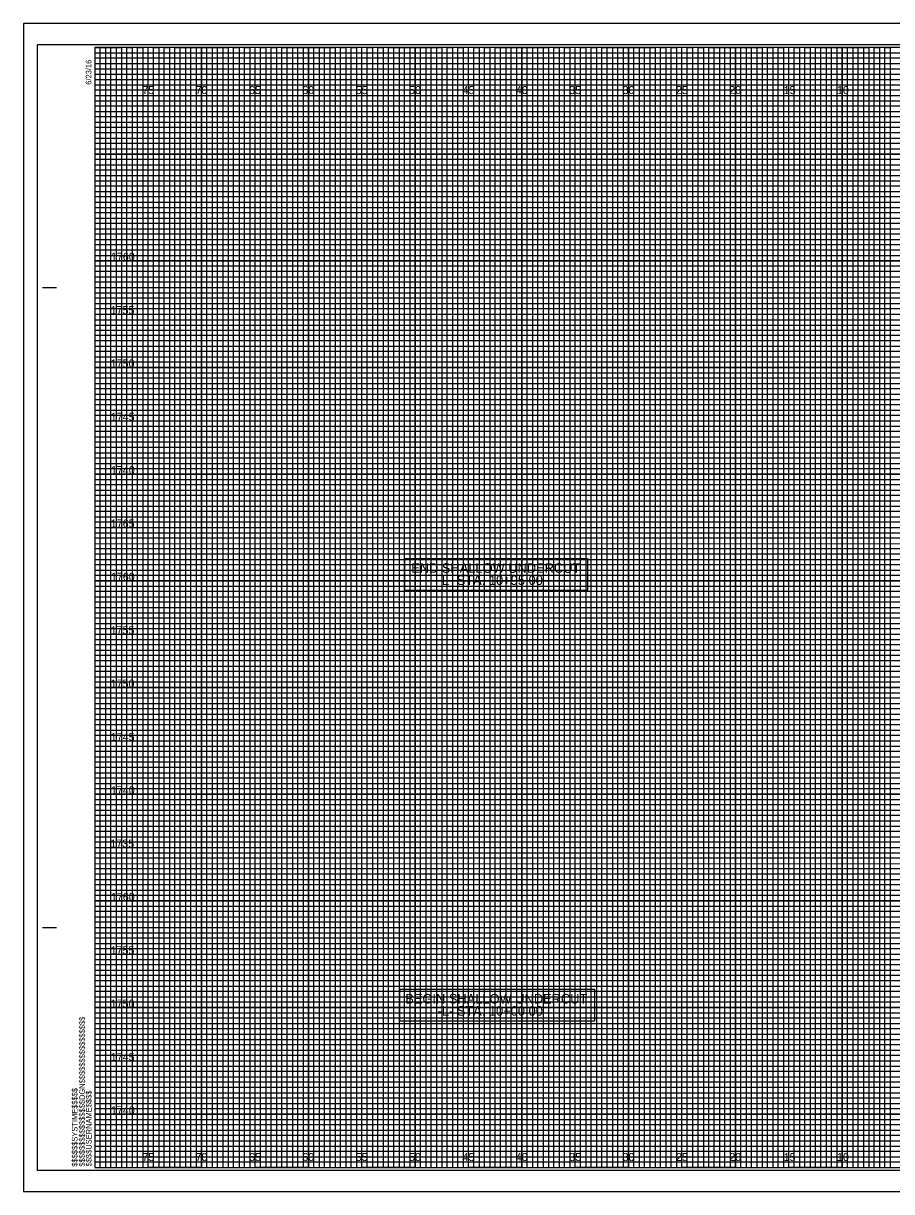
# Model space of a CAD drawing. Extents: x -7 to 162, y -2 to 107.
# Drawn here: x -6.7 to 74.6, y -2.3 to 107.3 of the extents above; entities that cross this region are included whole.
import ezdxf

# ---------------------------------------------------------------- set-up
doc = ezdxf.new("R2010")
doc.units = 0
for name, color, linetype in [('Exist XS Center Line Elevation Label', 7, 'Continuous'), ('Prop Grid Mask', 7, 'Continuous'), ('Prop XS Elevation Labels', 7, 'Continuous'), ('Prop XS Offset Labels', 7, 'Continuous'), ('Sheet Cross Section CELL', 7, 'Continuous'), ('Sheet Cross Section Grid Major CELL', 7, 'Continuous'), ('Sheet Cross Section Grid Middle CELL', 7, 'Continuous'), ('Sheet Cross Section Grid Minor 1 CELL', 7, 'Continuous'), ('Sheet Cross Section Grid Minor 2 CELL', 7, 'Continuous'), ('Sheet Cutting Line CELL', 7, 'Continuous'), ('Sheet DOT Grid CELL', 7, 'Continuous'), ('Sheet Plot Border Inside CELL', 7, 'Continuous'), ('Sheet Plot Border Outside CELL', 7, 'Continuous')]:
    doc.layers.add(name, color=color, linetype=linetype)

msp = doc.modelspace()

# ---------------------------------------------------------------- linework, layer by layer
at = {"layer": 'Prop Grid Mask'}
for points in [[(29.02, 57.09), (46.16, 57.09), (46.16, 54.1), (29.02, 54.1)], [(28.58, 16.72), (46.81, 16.72), (46.81, 13.74), (28.58, 13.74)]]:
    msp.add_lwpolyline(points, close=True, dxfattribs=at)
at = {"layer": 'Sheet Cross Section CELL'}
for p, q in [((-4.9, 82.5), (-3.65, 82.5)), ((-4.85, 82.5), (-3.6, 82.5)), ((-4.9, 22.5), (-3.65, 22.5)), ((-4.85, 22.5), (-3.6, 22.5)), ((0, 0), (0, 0)), ((0, 0), (0, 0)), ((0, 0), (0, 0)), ((0, 0), (0, 0)), ((0, 0), (0, 0)), ((0, 0), (0, 0)), ((0, 0), (0, 0))]:
    msp.add_line(p, q, dxfattribs=at)
msp.add_lwpolyline([(160, 105), (0, 105), (0, 0), (160, 0)], close=True, dxfattribs=at)
at = {"layer": 'Sheet Cross Section Grid Major CELL'}
for p, q in [((5, 105), (0, 105)), ((5, 0), (5, 105)), ((15, 105), (10, 105)), ((10, 105), (10, 0)), ((15, 0), (15, 105)), ((25, 105), (20, 105)), ((20, 105), (20, 0)), ((25, 0), (25, 105)), ((35, 105), (30, 105)), ((30, 105), (30, 0)), ((35, 0), (35, 105)), ((45, 105), (40, 105)), ((40, 105), (40, 0)), ((45, 0), (45, 105)), ((55, 105), (50, 105)), ((50, 105), (50, 0)), ((55, 0), (55, 105)), ((65, 105), (60, 105)), ((60, 105), (60, 0)), ((65, 0), (65, 105)), ((75, 105), (70, 105)), ((70, 105), (70, 0)), ((10, 0), (5, 0)), ((20, 0), (15, 0)), ((30, 0), (25, 0)), ((40, 0), (35, 0)), ((50, 0), (45, 0)), ((60, 0), (55, 0)), ((70, 0), (65, 0))]:
    msp.add_line(p, q, dxfattribs=at)
for points in [[(0, 100), (160, 100), (160, 95), (0, 95)], [(0, 90), (160, 90), (160, 85), (0, 85)], [(0, 80), (160, 80), (160, 75), (0, 75)], [(0, 70), (160, 70), (160, 65), (0, 65)], [(0, 60), (160, 60), (160, 55), (0, 55)], [(0, 50), (160, 50), (160, 45), (0, 45)], [(0, 40), (160, 40), (160, 35), (0, 35)], [(0, 30), (160, 30), (160, 25), (0, 25)], [(0, 20), (160, 20), (160, 15), (0, 15)], [(0, 10), (160, 10), (160, 5), (0, 5)]]:
    msp.add_lwpolyline(points, dxfattribs=at)
at = {"layer": 'Sheet Cross Section Grid Middle CELL'}
for points in [[(0, 105), (2.5, 105), (2.5, 0), (7.5, 0), (7.5, 105), (12.5, 105), (12.5, 0), (17.5, 0), (17.5, 105), (22.5, 105), (22.5, 0), (27.5, 0), (27.5, 105), (32.5, 105), (32.5, 0), (37.5, 0), (37.5, 105), (42.5, 105), (42.5, 0), (47.5, 0), (47.5, 105), (52.5, 105), (52.5, 0), (57.5, 0), (57.5, 105), (62.5, 105), (62.5, 0), (67.5, 0), (67.5, 105), (72.5, 105), (72.5, 0), (77.5, 0)], [(0, 102.5), (137.5, 102.5)], [(0, 92.5), (160, 92.5), (160, 97.5), (0, 97.5)], [(0, 82.5), (160, 82.5), (160, 87.5), (0, 87.5)], [(0, 72.5), (160, 72.5), (160, 77.5), (0, 77.5)], [(0, 62.5), (160, 62.5), (160, 67.5), (0, 67.5)], [(0, 52.5), (160, 52.5), (160, 57.5), (0, 57.5)], [(0, 42.5), (160, 42.5), (160, 47.5), (0, 47.5)], [(0, 32.5), (160, 32.5), (160, 37.5), (0, 37.5)], [(0, 22.5), (160, 22.5), (160, 27.5), (0, 27.5)], [(0, 12.5), (160, 12.5), (160, 17.5), (0, 17.5)], [(0, 2.5), (160, 2.5), (160, 7.5), (0, 7.5)]]:
    msp.add_lwpolyline(points, dxfattribs=at)
at = {"layer": 'Sheet Cross Section Grid Minor 1 CELL'}
for p, q in [((0, 104.5), (130, 104.5)), ((130, 103.99), (0, 103.99)), ((0, 103.99), (0, 103.5)), ((0, 103.5), (130, 103.5)), ((130, 102.95), (0, 102.95)), ((0, 102.95), (0, 102)), ((0, 102), (160, 102))]:
    msp.add_line(p, q, dxfattribs=at)
for points in [[(0, 101.5), (135, 101.5), (160, 101.5), (160, 101), (0, 101)], [(0, 100.5), (160, 100.5), (160, 99.5), (0, 99.5)], [(0, 99), (160, 99), (160, 98.5), (0, 98.49)], [(0, 98), (160, 98), (160, 97), (0, 97)], [(0, 96.5), (160, 96.5), (160, 96), (0, 96)], [(0, 95.5), (160, 95.5), (160, 94.5), (0, 94.5)], [(0, 94), (160, 94), (160, 93.5), (0, 93.5)], [(0, 93), (160, 93), (160, 92), (0, 92)], [(0, 91.5), (160, 91.5), (160, 91), (0, 91)], [(0, 90.5), (160, 90.5), (160, 89.5), (0, 89.5)], [(0, 89), (160, 89), (160, 88.5), (0, 88.5)], [(0, 88), (160, 88), (160, 86.98), (160, 86.5), (160, 86), (0, 86)], [(0, 87), (160, 87), (160, 86.5), (0, 86.5)], [(0, 85.5), (160, 85.5), (160, 84.5), (0, 84.52)], [(0, 84.52), (160, 84.5), (160, 84), (0, 84)], [(0, 83.5), (160, 83.5), (160, 83), (0, 83)], [(0, 82), (160, 82), (160, 81.5), (0, 81.5)], [(0, 81), (160, 81), (160, 80.5), (0, 80.5)], [(-0.04, 79.45), (160, 79.45), (160, 78.94), (-0.04, 78.94)], [(0, 78.5), (160, 78.5), (160, 78), (0, 78)], [(0, 77), (160, 77), (160, 76.5), (0, 76.5)], [(0, 76), (160, 76), (160, 75.5), (0, 75.5)], [(0, 74.5), (160, 74.5), (160, 74), (0, 74)], [(0, 73.5), (160, 73.5), (160, 73), (0, 73)], [(0, 72), (160, 72), (160, 71.5), (0, 71.5)], [(0, 71), (160, 71), (160, 70.5), (0, 70.5)], [(0, 69.5), (160, 69.5), (160, 68.99), (0, 69)], [(0, 68.5), (160, 68.5), (160, 68), (0, 68)], [(0, 67), (160, 67), (160, 66.5), (0, 66.5)], [(0, 66), (160, 66), (160, 65.5), (0, 65.5)], [(0, 64.5), (160, 64.5), (160, 64), (0, 64)], [(0, 63.5), (160, 63.5), (160, 63), (0, 63)], [(0, 62), (160, 62), (160, 61.5), (0, 61.5)], [(0, 61), (160, 61), (160, 60.5), (0, 60.5)], [(0, 59.5), (160, 59.5), (160, 59), (0, 59)], [(0, 58.5), (160.03, 58.45), (160, 58), (0, 58)], [(0, 57), (160, 57), (160, 56.5), (0, 56.5)], [(0, 56), (160, 56), (160, 55.5), (0, 55.5)], [(0, 54.5), (160, 54.5), (160, 54), (0, 54)], [(0, 53.5), (160, 53.5), (160, 53), (0, 53)], [(0, 52), (160, 52), (160, 51.5), (0, 51.5)], [(0, 51), (160, 51), (160, 50.5), (0, 50.5)], [(0, 49.5), (160, 49.5), (160, 49), (0, 49)], [(0, 48.5), (160, 48.5), (160, 48), (0, 48)], [(0, 47), (160, 47), (160, 46.5), (0, 46.5)], [(0, 46), (160, 46), (160, 45.5), (0, 45.5)], [(0, 44.5), (160, 44.5), (160, 44), (0, 44)], [(0, 43.5), (160, 43.5), (160, 43), (0, 43)], [(0, 42), (160, 42), (160, 41.5), (0, 41.5)], [(0, 41), (160, 41), (160, 40.5), (0, 40.5)], [(0, 39.5), (160, 39.5), (160, 38.99), (0, 39)], [(0, 38.5), (160, 38.5), (160, 38), (0, 38)], [(0, 37), (160, 37), (160, 36.5), (0, 36.5)], [(0, 36), (160, 36), (160, 35.5), (0, 35.5)], [(0, 34.5), (160, 34.5), (160, 34), (0, 34)], [(0, 33.5), (160, 33.5), (160, 33), (0, 33)], [(0, 32), (160, 32), (160, 31.5), (0, 31.5)], [(0, 31), (160, 31), (160, 30.5), (0, 30.5)], [(0, 29.5), (160, 29.5), (160, 29), (0, 29)], [(0, 28.5), (160.03, 28.46), (160, 28), (0, 28)], [(0, 27), (160, 27), (160, 26.5), (0, 26.5)], [(0, 26), (160, 26), (160, 25.5), (0, 25.5)], [(0, 24.5), (160, 24.5), (160, 24), (0, 24)], [(0, 23.5), (160, 23.5), (160, 23), (0, 23)], [(0, 22), (160, 22), (160, 21.5), (0, 21.5)], [(0, 21), (160, 21), (160, 20.5), (0, 20.5)], [(0, 19.5), (160, 19.5), (160, 19), (0, 19)], [(0, 18.5), (160, 18.5), (160, 18), (0, 18)], [(0, 17), (160, 17), (160, 16.5), (0, 16.5)], [(0, 16), (160, 16), (160, 15.5), (0, 15.5)], [(0, 14.5), (160, 14.5), (160, 14), (0, 14)], [(0, 13.5), (160, 13.5), (160, 13), (0, 13)], [(0, 12), (160, 12), (160, 11.5), (0, 11.5)], [(0, 11), (160, 11), (160, 10.5), (0, 10.5)], [(0, 9.5), (160, 9.5), (160, 9), (0, 9)], [(0, 8.5), (160, 8.5), (160, 8), (0, 8)], [(0, 7), (160, 7), (160, 6.5), (0, 6.5)], [(0, 6), (160, 6), (160, 5.5), (0, 5.5)], [(0, 4.5), (160, 4.5), (160, 4), (0, 4)], [(0, 3.5), (160, 3.5), (160, 3), (0, 3)], [(0, 2), (160, 2), (160, 1.5), (0, 1.5)], [(0, 1), (160, 1), (160, 0.5), (0, 0.5)]]:
    msp.add_lwpolyline(points, dxfattribs=at)
at = {"layer": 'Sheet Cross Section Grid Minor 2 CELL'}
for points in [[(0, 0), (0.5, 0), (0.5, 105), (1, 105), (1, 0)], [(1, 0), (1.5, 0), (1.5, 105), (2, 105), (2, 0)], [(2.5, 0), (3, 0), (3, 105), (3.5, 105), (3.5, 0)], [(3.5, 0), (4, 0), (4, 105), (4.5, 105), (4.5, 0)], [(5, 0), (5.5, 0), (5.5, 105), (6, 105), (6, 0)], [(6, 0), (6.5, 0), (6.5, 105), (7, 105), (7, 0)], [(7.5, 0), (8, 0), (8, 105), (8.5, 105), (8.5, 0)], [(8.5, 0), (9, 0), (9, 105), (9.5, 105), (9.5, 0)], [(10, 0), (10.5, 0), (10.5, 105), (11, 105), (11, 0)], [(11, 0), (11.5, 0), (11.5, 105), (12, 105), (12, 0)], [(12.5, 0), (13, 0), (13, 105), (13.5, 105), (13.5, 0)], [(13.5, 0), (14, 0), (14, 105), (14.5, 105), (14.5, 0)], [(15, 0), (15.5, 0), (15.5, 105), (16, 105), (16, 0)], [(16, 0), (16.5, 0), (16.5, 105), (17, 105), (17, 0)], [(17.5, 0), (18, 0), (18, 105), (18.5, 105), (18.5, 0)], [(18.5, 0), (19, 0), (19, 105), (19.5, 105), (19.5, 0)], [(20, 0), (20.5, 0), (20.5, 105), (21, 105), (21, 0)], [(21, 0), (21.5, 0), (21.5, 105), (22, 105), (22, 0)], [(22.5, 0), (23, 0), (23, 105), (23.5, 105), (23.5, 0)], [(23.5, 0), (24, 0), (24, 105), (24.5, 105), (24.5, 0)], [(25, 0), (25.5, 0), (25.5, 105), (26, 105), (26, 0)], [(26, 0), (26.5, 0), (26.5, 105), (27, 105), (27, 0)], [(27.5, 0), (28, 0), (28, 105), (28.5, 105), (28.5, 0)], [(28.5, 0), (29, 0), (29, 105), (29.5, 105), (29.5, 0)], [(30, 0), (30.5, 0), (30.5, 105), (31, 105), (31, 0)], [(31, 0), (31.5, 0), (31.5, 105), (32, 105), (32, 0)], [(32.5, 0), (33, 0), (33, 105), (33.5, 105), (33.5, 0)], [(33.5, 0), (34, 0), (34, 105), (34.5, 105), (34.5, 0)], [(35, 0), (35.5, 0), (35.5, 105), (36, 105), (36, 0)], [(36, 0), (36.5, 0), (36.5, 105), (37, 105), (37, 0)], [(37.5, 0), (38, 0), (38, 105), (38.5, 105), (38.5, 0)], [(38.5, 0), (39, 0), (39, 105), (39.5, 105), (39.5, 0)], [(40, 0), (40.5, 0), (40.5, 105), (41, 105), (41, 0)], [(41, 0), (41.5, 0), (41.5, 105), (42, 105), (42, 0)], [(42.5, 0), (43, 0), (43, 105), (43.5, 105), (43.5, 0)], [(43.5, 0), (44, 0), (44, 105), (44.5, 105), (44.5, 0)], [(45, 0), (45.5, 0), (45.5, 105), (46, 105), (46, 0)], [(46, 0), (46.5, 0), (46.5, 105), (47, 105), (47, 0)], [(47.5, 0), (48, 0), (48, 105), (48.5, 105), (48.5, 0)], [(48.5, 0), (49, 0), (49, 105), (49.5, 105), (49.5, 0)], [(50, 0), (50.5, 0), (50.5, 105), (51, 105), (51, 0)], [(51, 0), (51.5, 0), (51.5, 105), (52, 105), (52, 0)], [(52.5, 0), (53, 0), (53, 105), (53.5, 105), (53.5, 0)], [(53.5, 0), (54, 0), (54, 105), (54.5, 105), (54.5, 0)], [(55, 0), (55.5, 0), (55.5, 105), (56, 105), (56, 0)], [(56, 0), (56.5, 0), (56.5, 105), (57, 105), (57, 0)], [(57.5, 0), (58, 0), (58, 105), (58.5, 105), (58.5, 0)], [(58.5, 0), (59, 0), (59, 105), (59.5, 105), (59.5, 0)], [(60, 0), (60.5, 0), (60.5, 105), (61, 105), (61, 0)], [(61, 0), (61.5, 0), (61.5, 105), (62, 105), (62, 0)], [(62.5, 0), (63, 0), (63, 105), (63.5, 105), (63.5, 0)], [(63.5, 0), (64, 0), (64, 105), (64.5, 105), (64.5, 0)], [(65, 0), (65.5, 0), (65.5, 105), (66, 105), (66, 0)], [(66, 0), (66.5, 0), (66.5, 105), (67, 105), (67, 0)], [(67.5, 0), (68, 0), (68, 105), (68.5, 105), (68.5, 0)], [(68.5, 0), (69, 0), (69, 105), (69.5, 105), (69.5, 0)], [(70, 0), (70.5, 0), (70.5, 105), (71, 105), (71, 0)], [(71, 0), (71.5, 0), (71.5, 105), (72, 105), (72, 0)], [(72.5, 0), (73, 0), (73, 105), (73.5, 105), (73.5, 0)], [(73.5, 0), (74, 0), (74, 105), (74.5, 105), (74.5, 0)]]:
    msp.add_lwpolyline(points, dxfattribs=at)
at = {"layer": 'Sheet Cutting Line CELL'}
for p, q in [((161.65, 107.25), (-6.7, 107.25)), ((-6.7, 107.25), (-6.7, -2.25)), ((-6.7, -2.25), (161.65, -2.25))]:
    msp.add_line(p, q, dxfattribs=at)
at = {"layer": 'Sheet DOT Grid CELL'}
for p, q in [((5, 0), (5, 105)), ((10, 0), (10, 105)), ((15, 0), (15, 105)), ((20, 0), (20, 105)), ((25, 0), (25, 105)), ((30, 0), (30, 105)), ((35, 0), (35, 105)), ((40, 0), (40, 105)), ((45, 0), (45, 105)), ((50, 0), (50, 105)), ((55, 0), (55, 105)), ((60, 0), (60, 105)), ((65, 0), (65, 105)), ((70, 0), (70, 105)), ((0, 100), (160, 100)), ((0, 95), (160, 95)), ((0, 90), (160, 90)), ((0, 85), (160, 85)), ((0, 80), (160, 80)), ((0, 75), (160, 75)), ((0, 70), (160, 70)), ((0, 65), (160, 65)), ((0, 60), (160, 60)), ((0, 55), (160, 55)), ((0, 50), (160, 50)), ((0, 45), (160, 45)), ((0, 40), (160, 40)), ((0, 35), (160, 35)), ((0, 30), (160, 30)), ((0, 25), (160, 25)), ((0, 20), (160, 20)), ((0, 15), (160, 15)), ((0, 10), (160, 10)), ((0, 5), (160, 5))]:
    msp.add_line(p, q, dxfattribs=at)
at = {"layer": 'Sheet Plot Border Inside CELL'}
msp.add_lwpolyline([(-5.4, -0.25), (161.2, -0.25), (161.2, 105.25), (-5.4, 105.25)], close=True, dxfattribs=at)
at = {"layer": 'Sheet Plot Border Outside CELL'}
msp.add_lwpolyline([(-6.7, -2.25), (161.65, -2.25), (161.65, 107.25), (-6.7, 107.25)], close=True, dxfattribs=at)

# ---------------------------------------------------------------- texts
at = {"layer": 'Exist XS Center Line Elevation Label'}
for s, p in [('END SHALLOW UNDERCUT ', (29.63, 55.75)), ('-L- STA. 10+95.00', (32.1, 54.61)), ('BEGIN SHALLOW UNDERCUT ', (29.08, 15.38)), ('-L- STA. 10+00.00', (32.1, 14.24))]:
    msp.add_text(s, height=0.9, dxfattribs=at).set_placement(p)
at = {"layer": 'Prop XS Elevation Labels'}
for s, p in [('1760', (1.5, 85)), ('1755', (1.47, 80)), ('1750', (1.48, 75)), ('1745', (1.49, 70)), ('1740', (1.5, 65)), ('1765', (1.49, 60)), ('1760', (1.5, 55)), ('1755', (1.47, 50)), ('1750', (1.48, 45)), ('1745', (1.49, 40)), ('1740', (1.5, 35)), ('1735', (1.45, 30)), ('1760', (1.5, 25)), ('1755', (1.47, 20)), ('1750', (1.48, 15)), ('1745', (1.49, 10)), ('1740', (1.5, 5))]:
    msp.add_text(s, height=0.75, dxfattribs=at).set_placement(p)
at = {"layer": 'Prop XS Offset Labels'}
for s, p in [('75', (4.44, 100.62)), ('70', (9.43, 100.62)), ('65', (14.44, 100.62)), ('60', (19.43, 100.62)), ('55', (24.44, 100.62)), ('50', (29.43, 100.62)), ('45', (34.44, 100.62)), ('40', (39.43, 100.62)), ('35', (44.44, 100.62)), ('30', (49.43, 100.62)), ('25', (54.44, 100.62)), ('20', (59.43, 100.62)), ('15', (64.53, 100.62)), ('10', (69.52, 100.62)), ('75', (4.44, 0.62)), ('70', (9.43, 0.62)), ('65', (14.44, 0.62)), ('60', (19.43, 0.62)), ('55', (24.44, 0.62)), ('50', (29.43, 0.62)), ('45', (34.44, 0.62)), ('40', (39.43, 0.62)), ('35', (44.44, 0.62)), ('30', (49.43, 0.62)), ('25', (54.44, 0.62)), ('20', (59.43, 0.62)), ('15', (64.53, 0.62)), ('10', (69.52, 0.62))]:
    msp.add_text(s, height=0.75, dxfattribs=at).set_placement(p)
at = {"layer": 'Sheet Cross Section CELL'}
for s, p in [('6/23/16', (-0.33, 101.5)), ('$$$$$$$$$$$$$$$$DGN$$$$$$$$$$$$$$$$', (-0.94, 0.09)), ('$$$$$$SYSTIME$$$$$', (-1.63, 0.09)), ('$$$$USERNAME$$$$', (-0.31, 0.12))]:
    msp.add_text(s, height=0.525, rotation=90, dxfattribs=at).set_placement(p)

doc.saveas('drawing.dxf')
